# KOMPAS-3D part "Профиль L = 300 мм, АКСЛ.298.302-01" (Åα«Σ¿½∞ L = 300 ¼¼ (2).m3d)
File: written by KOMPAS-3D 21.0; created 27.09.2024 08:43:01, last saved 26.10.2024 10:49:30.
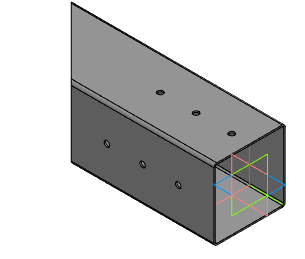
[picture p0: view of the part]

Document properties: Автор: Алексей Бочаров; Полное имя файла: C:\Users\Алексей Бочаров\YandexDisk\Соединения бруса\Соединения бруса\ТРИО\Профиль L = 300 мм (2).m3d

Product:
- Part/product: Профиль L = 300 мм  | designation АКСЛ.298.302-01
    Масса: 1.514806
    source file: АКСЛ.298.302 - Профиль L = 300 мм.cdw

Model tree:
1. Эскиз:1
2. Элемент выдавливания:1
     Расстояние 2 = 300
3. Плоскость под углом:1  (with: Элемент выдавливания:1)
     Угол = 45
4. Разрезать:1
5. Эскиз:2  (with: Разрезать:1)
6. Элемент выдавливания:2  (with: Разрезать:1)
     Расстояние 2 = 2
7. Эскиз:3  (with: Разрезать:1)
8. Элемент выдавливания:3  (with: Разрезать:1)
     Расстояние 2 = 2

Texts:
  АКСЛ.298.302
